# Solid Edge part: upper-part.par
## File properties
Author: Deepak Maini
Template: Part8.par
Last saved by: MYPC
Revision: 2
Application: Solid Edge
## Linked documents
Part8.par
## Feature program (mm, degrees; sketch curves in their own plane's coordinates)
part copy "unnamed PartCopy 1"
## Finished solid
Body 1: solid body, 23 faces, 60 edges, 40 vertices.
  Faces by surface: plane 9, cylinder 8, sphere 4, torus 2
  Edges by curve: circle 32, line 22, intersection 6
Bounding box of the edges (mm; curved faces can reach further): 68.011 x 85.812 x 33.994, from (-34.0057, -34, 0) to (34.0057, 51.8118, 33.994).
Cylindrical faces by radius (mm): R2.5 x4, R3 x1, R10.5 x1, R12.5 x2
Toroidal faces (ring radius, tube radius in mm): R-32.4919 r64.4976 x1, R-32.4919 r66.4976 x1
Spherical faces by radius (mm): R22 x1, R24 x1, R32 x1, R34 x1
Planar faces by outward normal: +y 3, -y 3, -z 3
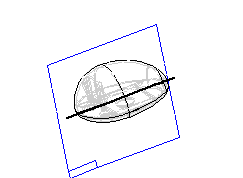
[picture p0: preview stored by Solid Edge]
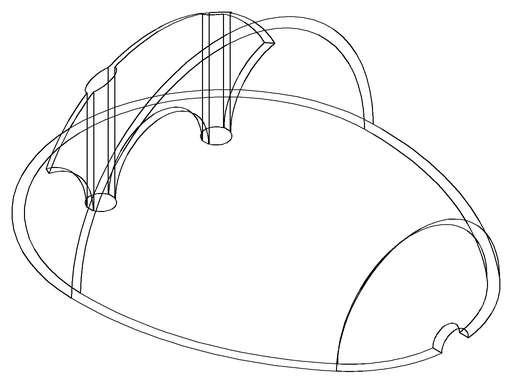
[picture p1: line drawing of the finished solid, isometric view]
